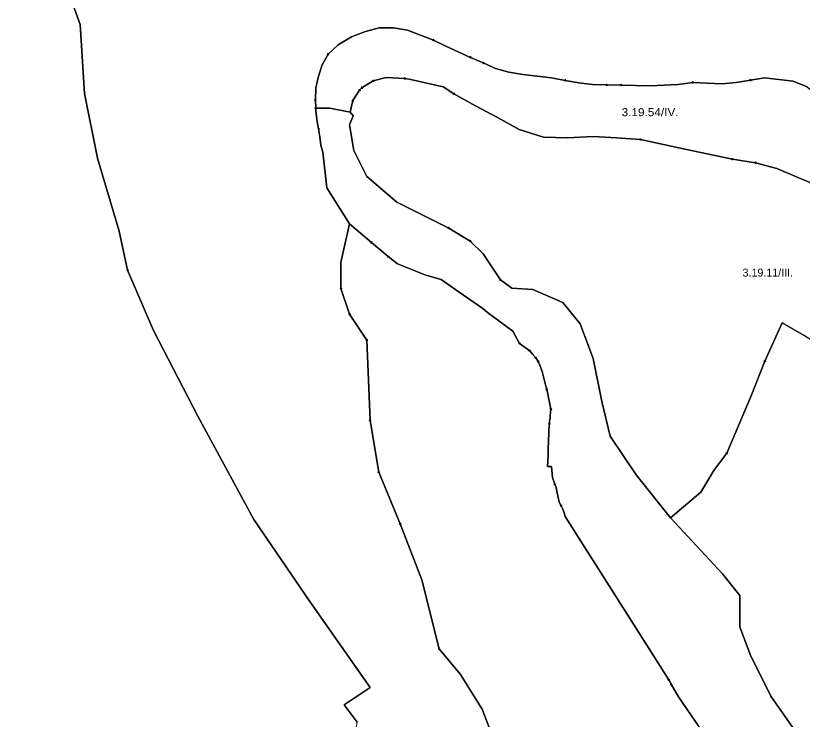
# Model space of a CAD drawing. Extents: x -650455 to -642254, y -1075222 to -1066610.
# Drawn here: x -647688 to -646705, y -1071216 to -1070337 of the extents above; entities that cross this region are included whole.
import ezdxf
from ezdxf.enums import TextEntityAlignment as Align

# ---------------------------------------------------------------- set-up
doc = ezdxf.new("R2010")
doc.units = 0
doc.header["$LTSCALE"] = 4
doc.header["$PDMODE"] = 32
doc.header["$PDSIZE"] = 2
for name, color, linetype, lineweight in [('1', 7, 'Continuous', 25), ('11', 7, 'Continuous', 13), ('12', 7, 'Continuous', 13), ('13', 7, 'Continuous', 13), ('14', 7, 'Continuous', 13)]:
    doc.layers.add(name, color=color, linetype=linetype, lineweight=lineweight)
doc.layers.add('2', color=7, linetype='Continuous')

msp = doc.modelspace()

# ---------------------------------------------------------------- linework, layer by layer
at = {"layer": '1'}
for points in [[(-647811.031, -1070119.811), (-647804.895, -1070123.56), (-647767.192, -1070139.719), (-647729.489, -1070139.719), (-647691.786, -1070161.263), (-647681.013, -1070188.194), (-647633.884, -1070234.65), (-647628.498, -1070288.512), (-647606.954, -1070347.759), (-647601.567, -1070433.938), (-647585.409, -1070514.73), (-647558.478, -1070606.295), (-647547.706, -1070654.771), (-647515.389, -1070730.177), (-647460.18, -1070837.227), (-647390.16, -1070966.495), (-647320.14, -1071068.832), (-647244.734, -1071176.555), (-647277.051, -1071198.1), (-647260.893, -1071219.644)], [(-647460.18, -1070837.227), (-647515.389, -1070730.177), (-647547.706, -1070654.771), (-647558.478, -1070606.295), (-647585.409, -1070514.73), (-647601.567, -1070433.938), (-647606.954, -1070347.759), (-647628.498, -1070288.512)], [(-647140.112, -1070434.285), (-647153.326, -1070425.707), (-647195.752, -1070416.202), (-647201.316, -1070415.275), (-647224.499, -1070414.232), (-647240.728, -1070418.173), (-647254.869, -1070426.866), (-647257.883, -1070429.88), (-647266.229, -1070442.863), (-647269.54, -1070457.526), (-647294.977, -1070452.484), (-647312.695, -1070452.484), (-647313.114, -1070441.961), (-647312.695, -1070426.797), (-647309.341, -1070412.193), (-647304.589, -1070398.148), (-647297.182, -1070384.941), (-647284.464, -1070373.132), (-647267.834, -1070363), (-647250.504, -1070356.361), (-647233.175, -1070351.959), (-647215.286, -1070351.889), (-647197.817, -1070354.894), (-647165.534, -1070367.192), (-647150.161, -1070374.949), (-647134.648, -1070382.006), (-647118.996, -1070388.924), (-647103.204, -1070395.842), (-647087.831, -1070402.62), (-647071.34, -1070407.302), (-647053.87, -1070410.446), (-647035.842, -1070412.473), (-647018.093, -1070414.499), (-647001.043, -1070417.644), (-646983.854, -1070420.788), (-646966.664, -1070422.954), (-646948.775, -1070423.304), (-646930.747, -1070423.513), (-646912.999, -1070424.002), (-646895.25, -1070424.491)], [(-646877.361, -1070423.583), (-646895.25, -1070424.491), (-646912.999, -1070424.002), (-646930.747, -1070423.513), (-646948.775, -1070423.304), (-646966.664, -1070422.954), (-646983.854, -1070420.788), (-647001.043, -1070417.644), (-647018.093, -1070414.499), (-647035.842, -1070412.473), (-647053.87, -1070410.446), (-647071.34, -1070407.302), (-647087.831, -1070402.62), (-647103.204, -1070395.842), (-647118.996, -1070388.924), (-647134.648, -1070382.006), (-647150.161, -1070374.949), (-647165.534, -1070367.192), (-647197.817, -1070354.894), (-647215.286, -1070351.889), (-647233.175, -1070351.959), (-647250.504, -1070356.361), (-647267.834, -1070363), (-647284.464, -1070373.132), (-647297.182, -1070384.941), (-647304.589, -1070398.148), (-647309.341, -1070412.193), (-647312.695, -1070426.797), (-647313.114, -1070441.961), (-647312.695, -1070452.484), (-647312.555, -1070456.006), (-647311.018, -1070468.933), (-647309.061, -1070478.227), (-647307.524, -1070488.359), (-647306.126, -1070498.491), (-647303.575, -1070507.298), (-647298.596, -1070551.76), (-647270.318, -1070596.869), (-647281.091, -1070645.345), (-647281.091, -1070677.662)], [(-646966, -1070765.187), (-646982.158, -1070722.098), (-647003.703, -1070695.167), (-647041.406, -1070679.008), (-647067.632, -1070677.48), (-647081.803, -1070666.889), (-647103.347, -1070634.572), (-647119.506, -1070618.414), (-647146.437, -1070602.256), (-647211.071, -1070569.939), (-647248.774, -1070537.621), (-647264.932, -1070505.305), (-647270.318, -1070472.988), (-647265.926, -1070462.007), (-647269.54, -1070457.526), (-647266.229, -1070442.863), (-647257.883, -1070429.88), (-647254.869, -1070426.866), (-647240.728, -1070418.173), (-647224.499, -1070414.232), (-647201.316, -1070415.275), (-647195.752, -1070416.202), (-647153.326, -1070425.707), (-647140.112, -1070434.285), (-647112.756, -1070449.238), (-647085.399, -1070464.192), (-647058.506, -1070479.145), (-647027.904, -1070488.534), (-646997.766, -1070489.346), (-646966.005, -1070487.607), (-646936.33, -1070489.578), (-646906.655, -1070491.548), (-646877.908, -1070497.692), (-646849.161, -1070503.835), (-646791.898, -1070516.123), (-646762.919, -1070520.643), (-646736.258, -1070527.946), (-646710.988, -1070538.494), (-646685.95, -1070549.043)], [(-646895.25, -1070424.491), (-646877.361, -1070423.583), (-646859.613, -1070422.675), (-646841.444, -1070420.229), (-646823.276, -1070420.998), (-646805.248, -1070421.766), (-646787.22, -1070420.299), (-646769.192, -1070417.294), (-646751.583, -1070414.289), (-646733.694, -1070416.456), (-646716.085, -1070418.622), (-646698.336, -1070425.54), (-646690.65, -1070432.527), (-646682.529, -1070440.373)], [(-646698.336, -1070425.54), (-646716.085, -1070418.622), (-646733.694, -1070416.456), (-646751.583, -1070414.289), (-646769.192, -1070417.294), (-646787.22, -1070420.299), (-646805.248, -1070421.766), (-646823.276, -1070420.998), (-646841.444, -1070420.229), (-646859.613, -1070422.675), (-646877.361, -1070423.583)], [(-646685.95, -1070549.043), (-646710.988, -1070538.494), (-646736.258, -1070527.946), (-646762.919, -1070520.643), (-646791.898, -1070516.123), (-646849.161, -1070503.835), (-646877.908, -1070497.692), (-646906.655, -1070491.548), (-646936.33, -1070489.578), (-646966.005, -1070487.607), (-646997.766, -1070489.346), (-647027.904, -1070488.534), (-647058.506, -1070479.145), (-647085.399, -1070464.192), (-647112.756, -1070449.238), (-647140.112, -1070434.285)], [(-647057.986, -1070746.402), (-647066.198, -1070731.193), (-647097.832, -1070707.62), (-647103.915, -1070702.754), (-647133.419, -1070682.375), (-647155.928, -1070666.71), (-647175.09, -1070661.235), (-647210.374, -1070647.091), (-647221.932, -1070637.966), (-647242.919, -1070620.324), (-647270.318, -1070596.869), (-647298.596, -1070551.76), (-647303.575, -1070507.298), (-647306.126, -1070498.491), (-647307.524, -1070488.359), (-647309.061, -1070478.227), (-647311.018, -1070468.933), (-647312.555, -1070456.006), (-647312.695, -1070452.484), (-647294.977, -1070452.484), (-647269.54, -1070457.526)], [(-647269.54, -1070457.526), (-647265.926, -1070462.007), (-647270.318, -1070472.988), (-647264.932, -1070505.305), (-647248.774, -1070537.621), (-647211.071, -1070569.939), (-647146.437, -1070602.256), (-647119.506, -1070618.414), (-647103.347, -1070634.572), (-647081.803, -1070666.889), (-647067.632, -1070677.48), (-647041.406, -1070679.008), (-647003.703, -1070695.167), (-646982.158, -1070722.098), (-646966, -1070765.187), (-646955.228, -1070819.048), (-646944.455, -1070862.138), (-646912.138, -1070910.613), (-646869.049, -1070964.475), (-646804.415, -1071034.495), (-646782.712, -1071061.526), (-646782.712, -1071100.526), (-646769.712, -1071135.193), (-646743.712, -1071187.194), (-646708.811, -1071237.149)], [(-647052.179, -1071341.506), (-647104.694, -1071203.486), (-647131.625, -1071160.397), (-647158.555, -1071128.08), (-647180.1, -1071041.901), (-647207.031, -1070971.881), (-647233.962, -1070907.247), (-647244.734, -1070842.613), (-647248.774, -1070742.296), (-647270.318, -1070709.979), (-647281.091, -1070677.662), (-647281.091, -1070645.345), (-647270.318, -1070596.869), (-647242.919, -1070620.324), (-647221.932, -1070637.966), (-647210.374, -1070647.091), (-647175.09, -1070661.235), (-647155.928, -1070666.71), (-647133.419, -1070682.375), (-647103.915, -1070702.754), (-647097.832, -1070707.62), (-647066.198, -1070731.193), (-647057.986, -1070746.402), (-647045.211, -1070755.527), (-647041.142, -1070760.07), (-647037.657, -1070764.462), (-647034.59, -1070769.039), (-647032.406, -1070773.523), (-647029.479, -1070781.609), (-647025.064, -1070799.849), (-647023.949, -1070803.682), (-647018.744, -1070828.381), (-647019.255, -1070833.353), (-647019.488, -1070836.49), (-647019.813, -1070839.952), (-647020.278, -1070843.414), (-647020.649, -1070846.876), (-647021.021, -1070850.338), (-647021.16, -1070854.358), (-647021.3, -1070858.331)], [(-647281.091, -1070677.662), (-647270.318, -1070709.979), (-647248.774, -1070742.296), (-647244.734, -1070842.613), (-647233.962, -1070907.247), (-647207.031, -1070971.881), (-647180.1, -1071041.901), (-647158.555, -1071128.08), (-647131.625, -1071160.397), (-647104.694, -1071203.486), (-647052.179, -1071341.506)], [(-646699.295, -1070738.147), (-646729.628, -1070720.814), (-646751.296, -1070768.481), (-646768.629, -1070811.815), (-646799.029, -1070883.683), (-646815.187, -1070905.227), (-646831.346, -1070932.158), (-646869.049, -1070964.475), (-646912.138, -1070910.613), (-646944.455, -1070862.138), (-646955.228, -1070819.048), (-646966, -1070765.187)], [(-646708.811, -1071237.149), (-646743.712, -1071187.194), (-646769.712, -1071135.193), (-646782.712, -1071100.526), (-646782.712, -1071061.526), (-646804.415, -1071034.495), (-646869.049, -1070964.475), (-646831.346, -1070932.158), (-646815.187, -1070905.227), (-646799.029, -1070883.683), (-646768.629, -1070811.815), (-646751.296, -1070768.481), (-646729.628, -1070720.814)], [(-646729.628, -1070720.814), (-646699.295, -1070738.147), (-646677.628, -1070751.147), (-646629.961, -1070759.814), (-646586.627, -1070781.481), (-646564.96, -1070798.814), (-646543.293, -1070842.148), (-646499.959, -1070898.482), (-646418.709, -1070853.523)], [(-646834.862, -1071224.003), (-646859.12, -1071188.198), (-646868.599, -1071172.329), (-646871.388, -1071167.008), (-647001.039, -1070962.935), (-647002.154, -1070958.358), (-647003.874, -1070953.78), (-647005.965, -1070949.25), (-647008.195, -1070944.719), (-647011.355, -1070931.033), (-647012.331, -1070926.688), (-647013.958, -1070922.343), (-647016.514, -1070913.979), (-647017.838, -1070900.335), (-647022.768, -1070900.162), (-647022.311, -1070887.151), (-647022.016, -1070878.731), (-647021.3, -1070858.331), (-647021.16, -1070854.358), (-647021.021, -1070850.338), (-647020.649, -1070846.876), (-647020.278, -1070843.414), (-647019.813, -1070839.952), (-647019.488, -1070836.49), (-647019.255, -1070833.353), (-647018.744, -1070828.381), (-647023.949, -1070803.682), (-647025.064, -1070799.849), (-647029.479, -1070781.609), (-647032.406, -1070773.523), (-647034.59, -1070769.039), (-647037.657, -1070764.462), (-647041.142, -1070760.07), (-647045.211, -1070755.527), (-647057.986, -1070746.402)], [(-647260.893, -1071219.644), (-647277.051, -1071198.1), (-647244.734, -1071176.555), (-647320.14, -1071068.832), (-647390.16, -1070966.495), (-647460.18, -1070837.227)], [(-647021.3, -1070858.331), (-647022.016, -1070878.731), (-647022.311, -1070887.151), (-647022.768, -1070900.162), (-647017.838, -1070900.335), (-647016.514, -1070913.979), (-647013.958, -1070922.343), (-647012.331, -1070926.688), (-647011.355, -1070931.033), (-647008.195, -1070944.719), (-647005.965, -1070949.25), (-647003.874, -1070953.78), (-647002.154, -1070958.358), (-647001.039, -1070962.935), (-646871.388, -1071167.008), (-646868.599, -1071172.329), (-646859.12, -1071188.198), (-646834.862, -1071224.003)]]:
    msp.add_lwpolyline(points, dxfattribs=at)
at = {"layer": '11'}
for p, q in [((-647118.996, -1070388.924), (-647103.204, -1070395.842)), ((-647248.774, -1070742.296), (-647270.318, -1070709.979))]:
    msp.add_line(p, q, dxfattribs=at)
for points in [[(-647628.498, -1070288.512), (-647606.954, -1070347.759), (-647601.567, -1070433.938), (-647585.409, -1070514.73), (-647558.478, -1070606.295), (-647547.706, -1070654.771)], [(-647313.114, -1070441.961), (-647312.695, -1070426.797), (-647309.341, -1070412.193), (-647304.589, -1070398.148), (-647297.182, -1070384.941), (-647284.464, -1070373.132), (-647267.834, -1070363), (-647250.504, -1070356.361), (-647233.175, -1070351.959), (-647215.286, -1070351.889), (-647197.817, -1070354.894), (-647165.534, -1070367.192)], [(-647165.534, -1070367.192), (-647150.161, -1070374.949), (-647134.648, -1070382.006), (-647118.996, -1070388.924)], [(-647103.204, -1070395.842), (-647087.831, -1070402.62), (-647071.34, -1070407.302), (-647053.87, -1070410.446), (-647035.842, -1070412.473), (-647018.093, -1070414.499), (-647001.043, -1070417.644), (-646983.854, -1070420.788), (-646966.664, -1070422.954), (-646948.775, -1070423.304)], [(-646948.775, -1070423.304), (-646930.747, -1070423.513), (-646912.999, -1070424.002), (-646895.25, -1070424.491), (-646877.361, -1070423.583), (-646859.613, -1070422.675), (-646841.444, -1070420.229), (-646823.276, -1070420.998), (-646805.248, -1070421.766), (-646787.22, -1070420.299), (-646769.192, -1070417.294), (-646751.583, -1070414.289), (-646733.694, -1070416.456), (-646716.085, -1070418.622), (-646698.336, -1070425.54)], [(-647270.318, -1070709.979), (-647281.091, -1070677.662), (-647281.091, -1070645.345), (-647270.318, -1070596.869), (-647298.596, -1070551.76), (-647303.575, -1070507.298), (-647306.126, -1070498.491), (-647307.524, -1070488.359), (-647309.061, -1070478.227), (-647311.018, -1070468.933), (-647312.555, -1070456.006), (-647312.695, -1070452.484), (-647313.114, -1070441.961)], [(-647547.706, -1070654.771), (-647515.389, -1070730.177), (-647460.18, -1070837.227), (-647390.16, -1070966.495), (-647320.14, -1071068.832), (-647244.734, -1071176.555), (-647277.051, -1071198.1), (-647260.893, -1071219.644), (-647266.279, -1071246.575), (-647283.784, -1071309.189), (-647287.224, -1071371.123), (-647299.444, -1071388.627), (-647318.899, -1071394.049), (-647345.688, -1071395.963), (-647362.91, -1071400.428), (-647370.883, -1071414.141), (-647371.84, -1071440.612), (-647371.84, -1071461.661)], [(-647207.031, -1070971.881), (-647233.962, -1070907.247), (-647244.734, -1070842.613), (-647248.774, -1070742.296)], [(-646992.931, -1071454.616), (-647052.179, -1071341.506), (-647104.694, -1071203.486), (-647131.625, -1071160.397), (-647158.555, -1071128.08), (-647180.1, -1071041.901), (-647207.031, -1070971.881)]]:
    msp.add_lwpolyline(points, dxfattribs=at)
for p in [(-647165.534, -1070367.192), (-647118.996, -1070388.924), (-647103.204, -1070395.842), (-646948.775, -1070423.304), (-647313.114, -1070441.961), (-647547.706, -1070654.771), (-647270.318, -1070709.979), (-647248.774, -1070742.296), (-647207.031, -1070971.881)]:
    msp.add_point(p, dxfattribs=at)
at = {"layer": '12'}
msp.add_lwpolyline([(-647283.784, -1071309.189), (-647266.279, -1071246.575), (-647260.893, -1071219.644), (-647277.051, -1071198.1), (-647244.734, -1071176.555), (-647320.14, -1071068.832), (-647390.16, -1070966.495), (-647460.18, -1070837.227), (-647515.389, -1070730.177), (-647547.706, -1070654.771), (-647558.478, -1070606.295), (-647585.409, -1070514.73), (-647601.567, -1070433.938), (-647606.954, -1070347.759), (-647628.498, -1070288.512)], dxfattribs=at)
at = {"layer": '13'}
for p, q in [((-647257.883, -1070429.88), (-647266.229, -1070442.863)), ((-647146.437, -1070602.256), (-647119.506, -1070618.414))]:
    msp.add_line(p, q, dxfattribs=at)
for points in [[(-646906.655, -1070491.548), (-646936.33, -1070489.578), (-646966.005, -1070487.607), (-646997.766, -1070489.346), (-647027.904, -1070488.534), (-647058.506, -1070479.145), (-647085.399, -1070464.192), (-647112.756, -1070449.238), (-647140.112, -1070434.285), (-647153.326, -1070425.707), (-647195.752, -1070416.202), (-647201.316, -1070415.275), (-647224.499, -1070414.232), (-647240.728, -1070418.173), (-647254.869, -1070426.866), (-647257.883, -1070429.88)], [(-647266.229, -1070442.863), (-647269.54, -1070457.526), (-647265.926, -1070462.007), (-647270.318, -1070472.988), (-647264.932, -1070505.305), (-647248.774, -1070537.621), (-647211.071, -1070569.939), (-647146.437, -1070602.256)], [(-646762.919, -1070520.643), (-646791.898, -1070516.123), (-646849.161, -1070503.835), (-646877.908, -1070497.692), (-646906.655, -1070491.548)], [(-646632.165, -1070565.271), (-646660.912, -1070559.591), (-646685.95, -1070549.043), (-646710.988, -1070538.494), (-646736.258, -1070527.946), (-646762.919, -1070520.643)], [(-647119.506, -1070618.414), (-647103.347, -1070634.572), (-647081.803, -1070666.889)], [(-647081.803, -1070666.889), (-647067.632, -1070677.48), (-647041.406, -1070679.008), (-647003.703, -1070695.167), (-646982.158, -1070722.098), (-646966, -1070765.187), (-646955.228, -1070819.048), (-646944.455, -1070862.138), (-646912.138, -1070910.613), (-646869.049, -1070964.475), (-646831.346, -1070932.158), (-646815.187, -1070905.227), (-646799.029, -1070883.683)], [(-646677.628, -1070751.147), (-646699.295, -1070738.147), (-646729.628, -1070720.814), (-646751.296, -1070768.481), (-646768.629, -1070811.815), (-646799.029, -1070883.683), (-646815.187, -1070905.227), (-646831.346, -1070932.158), (-646869.049, -1070964.475), (-646804.415, -1071034.495), (-646782.712, -1071061.526), (-646782.712, -1071100.526), (-646769.712, -1071135.193), (-646743.712, -1071187.194), (-646708.811, -1071237.149)], [(-646751.296, -1070768.481), (-646729.628, -1070720.814), (-646699.295, -1070738.147)], [(-646799.029, -1070883.683), (-646768.629, -1070811.815), (-646751.296, -1070768.481)]]:
    msp.add_lwpolyline(points, dxfattribs=at)
for p in [(-647257.883, -1070429.88), (-647266.229, -1070442.863), (-646906.655, -1070491.548), (-646762.919, -1070520.643), (-647146.437, -1070602.256), (-647119.506, -1070618.414), (-647081.803, -1070666.889), (-646751.296, -1070768.481), (-646799.029, -1070883.683)]:
    msp.add_point(p, dxfattribs=at)
at = {"layer": '14'}
for p, q in [((-647254.869, -1070426.866), (-647240.728, -1070418.173)), ((-647257.883, -1070429.88), (-647254.869, -1070426.866)), ((-646791.898, -1070516.123), (-646762.919, -1070520.643)), ((-647037.657, -1070764.462), (-647034.59, -1070769.039)), ((-647244.734, -1070842.613), (-647233.962, -1070907.247))]:
    msp.add_line(p, q, dxfattribs=at)
for points in [[(-647001.043, -1070417.644), (-647018.093, -1070414.499), (-647035.842, -1070412.473), (-647053.87, -1070410.446), (-647071.34, -1070407.302), (-647087.831, -1070402.62), (-647103.204, -1070395.842), (-647118.996, -1070388.924), (-647134.648, -1070382.006), (-647150.161, -1070374.949), (-647165.534, -1070367.192), (-647197.817, -1070354.894), (-647215.286, -1070351.889), (-647233.175, -1070351.959), (-647250.504, -1070356.361), (-647267.834, -1070363), (-647284.464, -1070373.132), (-647297.182, -1070384.941)], [(-647297.182, -1070384.941), (-647304.589, -1070398.148), (-647309.341, -1070412.193), (-647312.695, -1070426.797), (-647313.114, -1070441.961), (-647312.695, -1070452.484), (-647294.977, -1070452.484), (-647269.54, -1070457.526), (-647266.229, -1070442.863), (-647257.883, -1070429.88)], [(-647240.728, -1070418.173), (-647224.499, -1070414.232), (-647201.316, -1070415.275)], [(-647201.316, -1070415.275), (-647195.752, -1070416.202), (-647153.326, -1070425.707), (-647140.112, -1070434.285)], [(-646930.747, -1070423.513), (-646948.775, -1070423.304), (-646966.664, -1070422.954), (-646983.854, -1070420.788), (-647001.043, -1070417.644)], [(-646841.444, -1070420.229), (-646859.613, -1070422.675), (-646877.361, -1070423.583), (-646895.25, -1070424.491), (-646912.999, -1070424.002), (-646930.747, -1070423.513)], [(-646769.192, -1070417.294), (-646787.22, -1070420.299), (-646805.248, -1070421.766), (-646823.276, -1070420.998), (-646841.444, -1070420.229)], [(-646514.69, -1070497.343), (-646513.93, -1070496.996), (-646504.412, -1070489.744), (-646522.293, -1070490.738), (-646540.7, -1070486.685), (-646578.106, -1070489.302), (-646592.291, -1070489.809), (-646643.714, -1070491.413), (-646664.401, -1070487.107), (-646680.613, -1070473.935), (-646689.056, -1070460.931), (-646689.394, -1070455.19), (-646688.291, -1070450.623), (-646683.243, -1070441.891), (-646682.529, -1070440.373), (-646690.65, -1070432.527), (-646698.336, -1070425.54), (-646716.085, -1070418.622), (-646733.694, -1070416.456), (-646751.583, -1070414.289), (-646769.192, -1070417.294)], [(-647140.112, -1070434.285), (-647112.756, -1070449.238), (-647085.399, -1070464.192), (-647058.506, -1070479.145), (-647027.904, -1070488.534), (-646997.766, -1070489.346), (-646966.005, -1070487.607), (-646936.33, -1070489.578), (-646906.655, -1070491.548), (-646877.908, -1070497.692), (-646849.161, -1070503.835), (-646791.898, -1070516.123)], [(-646708.811, -1071237.149), (-646743.712, -1071187.194), (-646769.712, -1071135.193), (-646782.712, -1071100.526), (-646782.712, -1071061.526), (-646804.415, -1071034.495), (-646869.049, -1070964.475), (-646912.138, -1070910.613), (-646944.455, -1070862.138), (-646955.228, -1070819.048), (-646966, -1070765.187), (-646982.158, -1070722.098), (-647003.703, -1070695.167), (-647041.406, -1070679.008), (-647067.632, -1070677.48), (-647081.803, -1070666.889), (-647103.347, -1070634.572), (-647119.506, -1070618.414), (-647146.437, -1070602.256), (-647211.071, -1070569.939), (-647248.774, -1070537.621), (-647264.932, -1070505.305), (-647270.318, -1070472.988), (-647265.926, -1070462.007), (-647269.54, -1070457.526), (-647294.977, -1070452.484), (-647312.695, -1070452.484)], [(-647312.695, -1070452.484), (-647312.555, -1070456.006), (-647311.018, -1070468.933), (-647309.061, -1070478.227)], [(-647309.061, -1070478.227), (-647307.524, -1070488.359), (-647306.126, -1070498.491), (-647303.575, -1070507.298), (-647298.596, -1070551.76), (-647270.318, -1070596.869), (-647242.919, -1070620.324), (-647221.932, -1070637.966)], [(-646762.919, -1070520.643), (-646736.258, -1070527.946), (-646710.988, -1070538.494), (-646685.95, -1070549.043)], [(-647242.919, -1070620.324), (-647270.318, -1070596.869), (-647281.091, -1070645.345), (-647281.091, -1070677.662)], [(-647057.986, -1070746.402), (-647066.198, -1070731.193), (-647097.832, -1070707.62), (-647103.915, -1070702.754), (-647133.419, -1070682.375), (-647155.928, -1070666.71), (-647175.09, -1070661.235), (-647210.374, -1070647.091), (-647221.932, -1070637.966), (-647242.919, -1070620.324)], [(-647221.932, -1070637.966), (-647210.374, -1070647.091), (-647175.09, -1070661.235), (-647155.928, -1070666.71), (-647133.419, -1070682.375), (-647103.915, -1070702.754), (-647097.832, -1070707.62), (-647066.198, -1070731.193), (-647057.986, -1070746.402), (-647045.211, -1070755.527)], [(-647281.091, -1070677.662), (-647270.318, -1070709.979), (-647248.774, -1070742.296), (-647244.734, -1070842.613)], [(-647023.949, -1070803.682), (-647025.064, -1070799.849), (-647029.479, -1070781.609), (-647032.406, -1070773.523), (-647034.59, -1070769.039), (-647037.657, -1070764.462), (-647041.142, -1070760.07), (-647045.211, -1070755.527), (-647057.986, -1070746.402)], [(-647045.211, -1070755.527), (-647041.142, -1070760.07), (-647037.657, -1070764.462)], [(-647034.59, -1070769.039), (-647032.406, -1070773.523), (-647029.479, -1070781.609), (-647025.064, -1070799.849), (-647023.949, -1070803.682), (-647018.744, -1070828.381)], [(-647020.649, -1070846.876), (-647020.278, -1070843.414), (-647019.813, -1070839.952), (-647019.488, -1070836.49), (-647019.255, -1070833.353), (-647018.744, -1070828.381), (-647023.949, -1070803.682)], [(-647018.744, -1070828.381), (-647019.255, -1070833.353), (-647019.488, -1070836.49), (-647019.813, -1070839.952), (-647020.278, -1070843.414), (-647020.649, -1070846.876), (-647021.021, -1070850.338), (-647021.16, -1070854.358), (-647021.3, -1070858.331), (-647022.016, -1070878.731), (-647022.311, -1070887.151), (-647022.768, -1070900.162), (-647017.838, -1070900.335), (-647016.514, -1070913.979), (-647013.958, -1070922.343)], [(-647005.965, -1070949.25), (-647008.195, -1070944.719), (-647011.355, -1070931.033), (-647012.331, -1070926.688), (-647013.958, -1070922.343), (-647016.514, -1070913.979), (-647017.838, -1070900.335), (-647022.768, -1070900.162), (-647022.311, -1070887.151), (-647022.016, -1070878.731), (-647021.3, -1070858.331), (-647021.16, -1070854.358), (-647021.021, -1070850.338), (-647020.649, -1070846.876)], [(-647233.962, -1070907.247), (-647207.031, -1070971.881), (-647180.1, -1071041.901), (-647158.555, -1071128.08)], [(-647013.958, -1070922.343), (-647012.331, -1070926.688), (-647011.355, -1070931.033), (-647008.195, -1070944.719), (-647005.965, -1070949.25), (-647003.874, -1070953.78), (-647002.154, -1070958.358), (-647001.039, -1070962.935), (-646871.388, -1071167.008), (-646868.599, -1071172.329)], [(-646871.388, -1071167.008), (-647001.039, -1070962.935), (-647002.154, -1070958.358), (-647003.874, -1070953.78), (-647005.965, -1070949.25)], [(-647158.555, -1071128.08), (-647131.625, -1071160.397), (-647104.694, -1071203.486), (-647052.179, -1071341.506), (-646992.931, -1071454.616), (-646885.208, -1071621.587)], [(-646829.299, -1071242.546), (-646824.502, -1071239.296), (-646834.862, -1071224.003), (-646859.12, -1071188.198), (-646868.599, -1071172.329), (-646871.388, -1071167.008)], [(-646868.599, -1071172.329), (-646859.12, -1071188.198), (-646834.862, -1071224.003)]]:
    msp.add_lwpolyline(points, dxfattribs=at)
for p in [(-647297.182, -1070384.941), (-647240.728, -1070418.173), (-647201.316, -1070415.275), (-647001.043, -1070417.644), (-646841.444, -1070420.229), (-646769.192, -1070417.294), (-647257.883, -1070429.88), (-647254.869, -1070426.866), (-646930.747, -1070423.513), (-647140.112, -1070434.285), (-647312.695, -1070452.484), (-647309.061, -1070478.227), (-646791.898, -1070516.123), (-646762.919, -1070520.643), (-647242.919, -1070620.324), (-647221.932, -1070637.966), (-647281.091, -1070677.662), (-647057.986, -1070746.402), (-647045.211, -1070755.527), (-647037.657, -1070764.462), (-647034.59, -1070769.039), (-647023.949, -1070803.682), (-647018.744, -1070828.381), (-647244.734, -1070842.613), (-647020.649, -1070846.876), (-647233.962, -1070907.247), (-647013.958, -1070922.343), (-647005.965, -1070949.25), (-647158.555, -1071128.08), (-646871.388, -1071167.008), (-646868.599, -1071172.329)]:
    msp.add_point(p, dxfattribs=at)

# ---------------------------------------------------------------- texts
at = {"layer": '2', "width": 1.1}
msp.add_text('3.19.54/IV.', height=10, dxfattribs=at).set_placement((-646894.736, -1070462.35), align=Align.CENTER)
at = {"layer": '2'}
msp.add_text('3.19.11/III.', height=10, dxfattribs=at).set_placement((-646747.586, -1070662.908), align=Align.CENTER)

doc.saveas('drawing.dxf')
